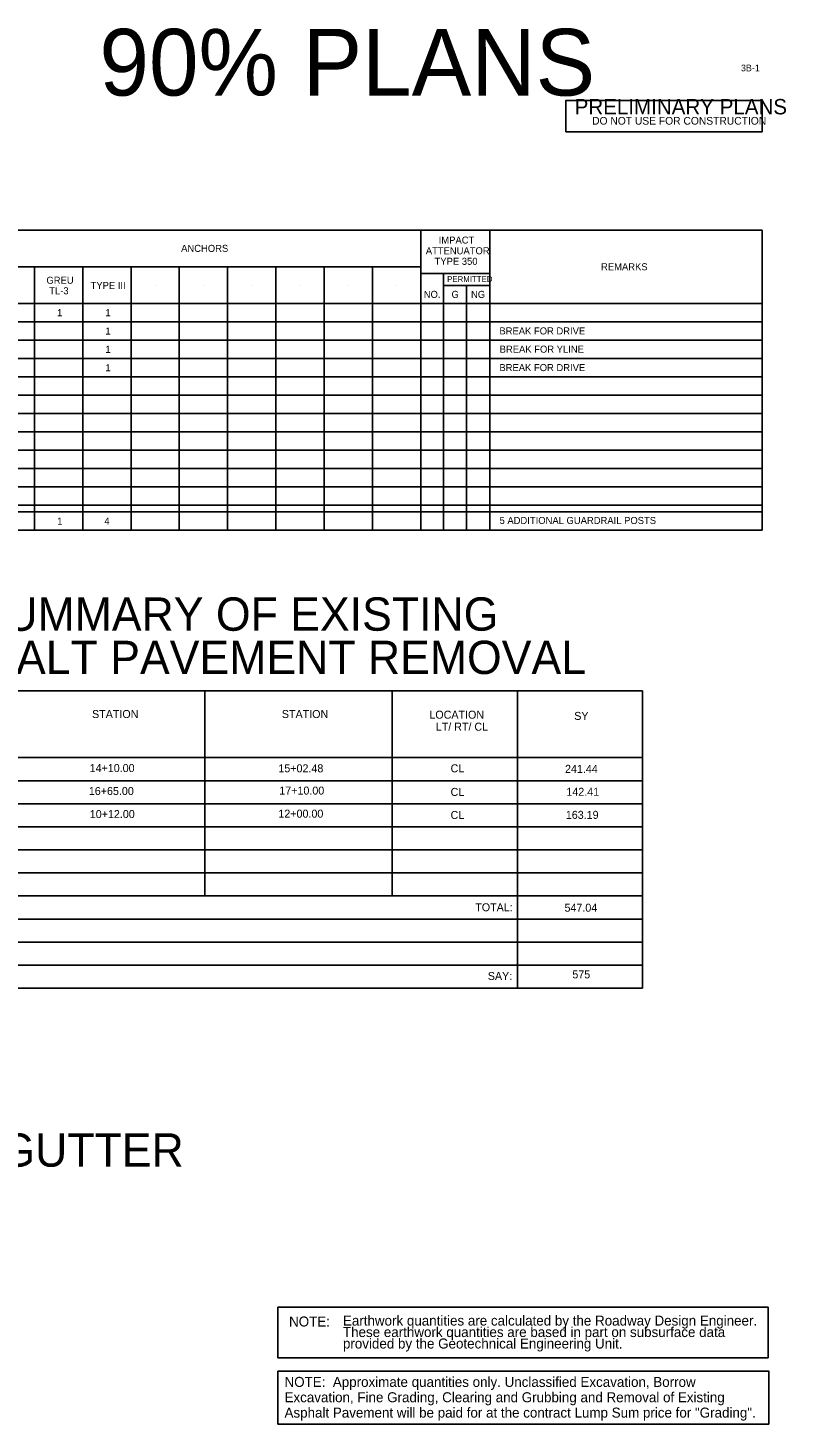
# Model space of a CAD drawing. Extents: x 3532015 to 3532162, y 657834 to 657939.
# Drawn here: x 3532105.3 to 3532162.2, y 657834.7 to 657939.4 of the extents above; entities that cross this region are included whole.
import ezdxf

# ---------------------------------------------------------------- set-up
doc = ezdxf.new("R2010")
doc.units = 0
for name, color, linetype in [('Old_Level_1', 7, 'Continuous'), ('Old_Level_41', 7, 'Continuous'), ('Old_Level_44', 7, 'Continuous'), ('Old_Level_52', 7, 'Continuous'), ('Sheet Summary Combination CELL', 7, 'Continuous'), ('Sheet Summary Combination Grid CELL', 7, 'Continuous'), ('Sheet Summary Earthwork CELL', 7, 'Continuous'), ('Sheet Summary Guardrail CELL', 7, 'Continuous')]:
    doc.layers.add(name, color=color, linetype=linetype)

msp = doc.modelspace()

# ---------------------------------------------------------------- linework, layer by layer
at = {"layer": 'Old_Level_1'}
msp.add_lwpolyline([(3532145.65, 657931.61), (3532145.65, 657933.96), (3532160.35, 657933.96), (3532160.35, 657931.61)], close=True, dxfattribs=at)
at = {"layer": 'Old_Level_41'}
for p, q in [((3532095.12, 657882.96), (3532151.39, 657882.96)), ((3532095.12, 657881.23), (3532151.39, 657881.23)), ((3532151.39, 657879.5), (3532095.12, 657879.5)), ((3532095.12, 657877.77), (3532151.39, 657877.77)), ((3532151.39, 657876.05), (3532095.12, 657876.05)), ((3532151.39, 657872.59), (3532095.12, 657872.59)), ((3532095.12, 657870.86), (3532151.39, 657870.86)), ((3532151.39, 657869.13), (3532095.12, 657869.13))]:
    msp.add_line(p, q, dxfattribs=at)
at = {"layer": 'Old_Level_52'}
msp.add_lwpolyline([(3532124.06, 657838.7), (3532160.85, 657838.7), (3532160.85, 657834.72), (3532124.06, 657834.72)], close=True, dxfattribs=at)
at = {"layer": 'Sheet Summary Combination CELL'}
for p, q in [((3532123.37, 657889.68), (3532123.37, 657889.68)), ((3532124.62, 657889.66), (3532124.62, 657889.66)), ((3532126.43, 657889.7), (3532126.43, 657889.7)), ((3532127.55, 657889.68), (3532127.55, 657889.68))]:
    msp.add_line(p, q, dxfattribs=at)
at = {"layer": 'Sheet Summary Combination Grid CELL'}
for p, q in [((3532095.12, 657889.69), (3532151.39, 657889.69)), ((3532118.57, 657889.69), (3532118.57, 657874.32)), ((3532132.63, 657889.69), (3532132.63, 657874.32)), ((3532142.01, 657889.69), (3532142.01, 657867.4)), ((3532151.39, 657889.69), (3532151.39, 657867.4)), ((3532095.12, 657884.69), (3532151.39, 657884.69)), ((3532095.12, 657874.32), (3532151.39, 657874.32)), ((3532095.12, 657867.4), (3532151.39, 657867.4))]:
    msp.add_line(p, q, dxfattribs=at)
at = {"layer": 'Sheet Summary Earthwork CELL'}
msp.add_lwpolyline([(3532124.06, 657843.48), (3532160.8, 657843.48), (3532160.8, 657839.7), (3532124.06, 657839.7)], close=True, dxfattribs=at)
at = {"layer": 'Sheet Summary Guardrail CELL'}
for p, q in [((3532015.54, 657924.25), (3532160.37, 657924.25)), ((3532134.76, 657924.25), (3532134.76, 657901.74)), ((3532139.93, 657924.25), (3532139.93, 657901.74)), ((3532160.37, 657924.25), (3532160.37, 657901.74)), ((3532134.76, 657921.5), (3532083.95, 657921.5)), ((3532105.81, 657921.5), (3532105.81, 657901.74)), ((3532109.43, 657921.5), (3532109.43, 657901.74)), ((3532113.04, 657921.5), (3532113.04, 657901.74)), ((3532116.66, 657921.5), (3532116.66, 657901.74)), ((3532120.28, 657921.5), (3532120.28, 657901.74)), ((3532123.9, 657921.5), (3532123.9, 657901.74)), ((3532127.52, 657921.5), (3532127.52, 657901.74)), ((3532131.14, 657921.5), (3532131.14, 657901.74)), ((3532138.95, 657921.53), (3532138.95, 657921.53)), ((3532107.62, 657920.12), (3532107.62, 657920.12)), ((3532114.85, 657920.12), (3532114.85, 657920.12)), ((3532118.47, 657920.12), (3532118.47, 657920.12)), ((3532122.09, 657920.12), (3532122.09, 657920.12)), ((3532125.71, 657920.12), (3532125.71, 657920.12)), ((3532129.33, 657920.12), (3532129.33, 657920.12)), ((3532132.95, 657920.12), (3532132.95, 657920.12)), ((3532134.76, 657920.98), (3532139.93, 657920.98)), ((3532136.48, 657920.98), (3532136.48, 657901.74)), ((3532136.48, 657920.1), (3532139.93, 657920.1)), ((3532138.2, 657920.1), (3532138.2, 657901.74)), ((3532015.54, 657918.75), (3532160.37, 657918.75)), ((3532015.54, 657917.37), (3532160.37, 657917.37)), ((3532015.54, 657916), (3532160.37, 657916)), ((3532015.54, 657914.62), (3532160.37, 657914.62)), ((3532015.54, 657913.25), (3532160.37, 657913.25)), ((3532015.54, 657911.87), (3532160.37, 657911.87)), ((3532015.54, 657910.5), (3532160.37, 657910.5)), ((3532015.54, 657909.12), (3532160.37, 657909.12)), ((3532015.54, 657907.75), (3532160.37, 657907.75)), ((3532015.54, 657906.37), (3532160.37, 657906.37)), ((3532015.54, 657905), (3532160.37, 657905)), ((3532015.54, 657903.62), (3532160.37, 657903.62)), ((3532015.54, 657903.11), (3532160.37, 657903.11)), ((3532015.54, 657901.74), (3532160.37, 657901.74))]:
    msp.add_line(p, q, dxfattribs=at)

# ---------------------------------------------------------------- texts
at = {"layer": 'Old_Level_1'}
for s, height, p in [('90% PLANS', 5, (3532110.67, 657934.33)), ('PRELIMINARY PLANS', 1.152, (3532146.3, 657932.92)), ('DO NOT USE FOR CONSTRUCTION', 0.576, (3532147.61, 657932.15))]:
    msp.add_text(s, height=height, dxfattribs=at).set_placement(p)
at = {"layer": 'Old_Level_44'}
msp.add_text('3B-1', height=0.5, dxfattribs=at).set_placement((3532158.77, 657936.15))
at = {"layer": 'Old_Level_52'}
for s, p in [('NOTE:  Approximate quantities only. Unclassified Excavation, Borrow', (3532124.55, 657837.51)), ('Excavation, Fine Grading, Clearing and Grubbing and Removal of Existing', (3532124.55, 657836.36)), ('Asphalt Pavement will be paid for at the contract Lump Sum price for "Grading".', (3532124.55, 657835.21))]:
    msp.add_text(s, height=0.75, rotation=0, dxfattribs=at).set_placement(p)
at = {"layer": 'Sheet Summary Combination CELL'}
for s, p in [('SUMMARY OF EXISTING', (3532101.39, 657894.2)), ('ASPHALT PAVEMENT REMOVAL', (3532095.32, 657890.95))]:
    msp.add_text(s, height=2.5, rotation=0.0119, dxfattribs=at).set_placement(p)
for s, p in [('STATION', (3532110.12, 657887.66)), ('STATION', (3532124.35, 657887.66)), ('LOCATION', (3532135.41, 657887.61)), ('LT/ RT/ CL', (3532135.89, 657886.71)), ('14+10.00', (3532109.94, 657883.61)), ('15+02.48', (3532124.09, 657883.59)), ('CL', (3532137, 657883.59)), ('241.44', (3532145.58, 657883.55)), ('16+65.00', (3532109.88, 657881.89)), ('17+10.00', (3532124.16, 657881.92)), ('CL', (3532137, 657881.82)), ('142.41', (3532145.68, 657881.83)), ('10+12.00', (3532109.95, 657880.16)), ('12+00.00', (3532124.09, 657880.19)), ('CL', (3532137, 657880.09)), ('163.19', (3532145.64, 657880.1)), ('TOTAL:', (3532138.85, 657873.17)), ('547.04', (3532145.54, 657873.14)), ('575', (3532146.13, 657868.14)), ('SAY:', (3532139.79, 657868.02))]:
    msp.add_text(s, height=0.6, dxfattribs=at).set_placement(p)
at = {"layer": 'Sheet Summary Combination Grid CELL'}
msp.add_text('SY', height=0.6, dxfattribs=at).set_placement((3532146.27, 657887.52))
at = {"layer": 'Sheet Summary Earthwork CELL'}
for s, p in [('NOTE:', (3532124.89, 657842.04)), ('Earthwork quantities are calculated by the Roadway Design Engineer. ', (3532128.93, 657842.11)), ('These earthwork quantities are based in part on subsurface data ', (3532128.93, 657841.25)), ('provided by the Geotechnical Engineering Unit.', (3532128.93, 657840.39))]:
    msp.add_text(s, height=0.75, dxfattribs=at).set_placement(p)
at = {"layer": 'Sheet Summary Guardrail CELL'}
for s, height, p in [('ANCHORS', 0.528, (3532116.8, 657922.61)), ('IMPACT', 0.528, (3532136.11, 657923.23)), ('ATTENUATOR', 0.528, (3532135.14, 657922.43)), ('TYPE 350', 0.528, (3532135.8, 657921.64)), ('REMARKS', 0.528, (3532148.28, 657921.23)), ('GREU', 0.528, (3532106.7, 657920.22)), ('TYPE III', 0.528, (3532110.01, 657919.83)), ('PERMITTED', 0.44, (3532136.74, 657920.35)), ('TL-3', 0.528, (3532106.91, 657919.43)), ('NO.', 0.528, (3532134.99, 657919.16)), ('G', 0.528, (3532137.07, 657919.16)), ('NG', 0.528, (3532138.53, 657919.16)), ('1', 0.528, (3532107.5, 657917.79)), ('1', 0.528, (3532111.12, 657917.79)), ('1', 0.528, (3532111.12, 657916.41)), ('BREAK FOR DRIVE', 0.528, (3532140.66, 657916.42)), ('1', 0.528, (3532111.12, 657915.04)), ('BREAK FOR YLINE', 0.528, (3532140.68, 657915.05)), ('1', 0.528, (3532111.12, 657913.66)), ('BREAK FOR DRIVE', 0.528, (3532140.66, 657913.67)), ('1', 0.528, (3532107.51, 657902.16)), ('4', 0.528, (3532111.04, 657902.16)), ('5 ADDITIONAL GUARDRAIL POSTS', 0.528, (3532140.67, 657902.21))]:
    msp.add_text(s, height=height, dxfattribs=at).set_placement(p)
msp.add_text('SUMMARY OF SHOULDER BERM GUTTER', height=2.5, rotation=0.0119, dxfattribs=at).set_placement((3532049.57, 657854.01))

doc.saveas('drawing.dxf')
